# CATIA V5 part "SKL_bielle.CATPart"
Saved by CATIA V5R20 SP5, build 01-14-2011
Part number: SKL_bielle
Publications: "Point.3", "Point.1", "Droite.1", "Plan.1", "Droite.2", "Droite.3"
Bounding box of the stored display mesh (mm): x 0 to 0, y 6 to 41, z -10 to 10
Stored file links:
  F:\Catia_finish\SKL_bielle.CATPart
  F:\Catia_finish\ASS_SKL.CATProduct
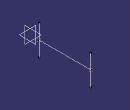
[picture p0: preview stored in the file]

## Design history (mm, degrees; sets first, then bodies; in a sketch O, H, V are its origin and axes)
Set1
  Point1: linked copy from another document
  Point2: linked copy from another document
  Plane1: linked copy from another document
Set2
  Point3: (0, 0, 0), relative to Point1
  Point4: (0, 0, 0), relative to Point2
  Line1: type PtPt, FirstPoint Point3, SecondPoint Point4
  Plane2: type Offset, RefPlane Plane1, Offset 0
  Line2: type Normal, RefPoint Point4, RefSkin Plane2, Start -10, End 10
  Line3: type Normal, RefPoint Point1, RefSkin Plane2, Start -10, End 10
Body1 (main body)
